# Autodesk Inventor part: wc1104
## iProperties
Shininess: 64.0
Length Units: 11272
Angle Units: 11279
Time Units: 11290
Mass Units: 11286
Length Display Precision: 3
Angle Display Precision: 2
Compacted: True
Part Number: wc1104
Document SubType Name: Modeling
Created: 2004-08
Designer: John Blackburn
Manufacturer: Standard
Standards Organization: Custom
Material: Stainless Steel, Austenitic
Density: 0.0
Volumn: 0.0
Area: 0.0
PropertySet Name: Model Information
Control State: 0
Master: False
Checked Out: False
Author: John Blackburn
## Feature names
1. Base1
